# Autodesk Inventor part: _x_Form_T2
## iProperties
Created: 2005-11
Part Number: _x_Form_T2
Document SubType Name: Modeling
Designer: IMA/Frank
Manufacturer: Standard
Standards Organization: Custom
Author: IMA/Frank
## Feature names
1. Trennen1
2. Abgeleiteter Körper1 [Tagging]
